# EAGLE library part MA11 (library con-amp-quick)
AMP QUICK CONNECTOR
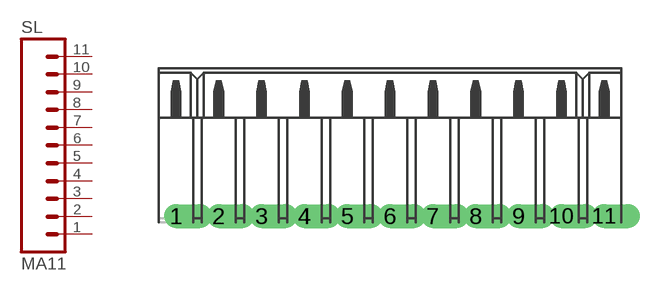
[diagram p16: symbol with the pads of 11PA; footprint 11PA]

Designator prefix SL

## MA11  [11PA]
1  1  pas
2  2  pas
3  3  pas
4  4  pas
5  5  pas
6  6  pas
7  7  pas
8  8  pas
9  9  pas
10  10  pas
11  11  pas

## Footprint 11PA (pad centres in mm)
AMP QUICK CONNECTOR
drill 0.914 offset: 1 -12.7,0; 2 -10.16,0; 3 -7.62,0; 4 -5.08,0; 5 -2.54,0; 6 0,0; 7 2.54,0; 8 5.08,0; 9 7.62,0; 10 10.16,0; 11 12.7,0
